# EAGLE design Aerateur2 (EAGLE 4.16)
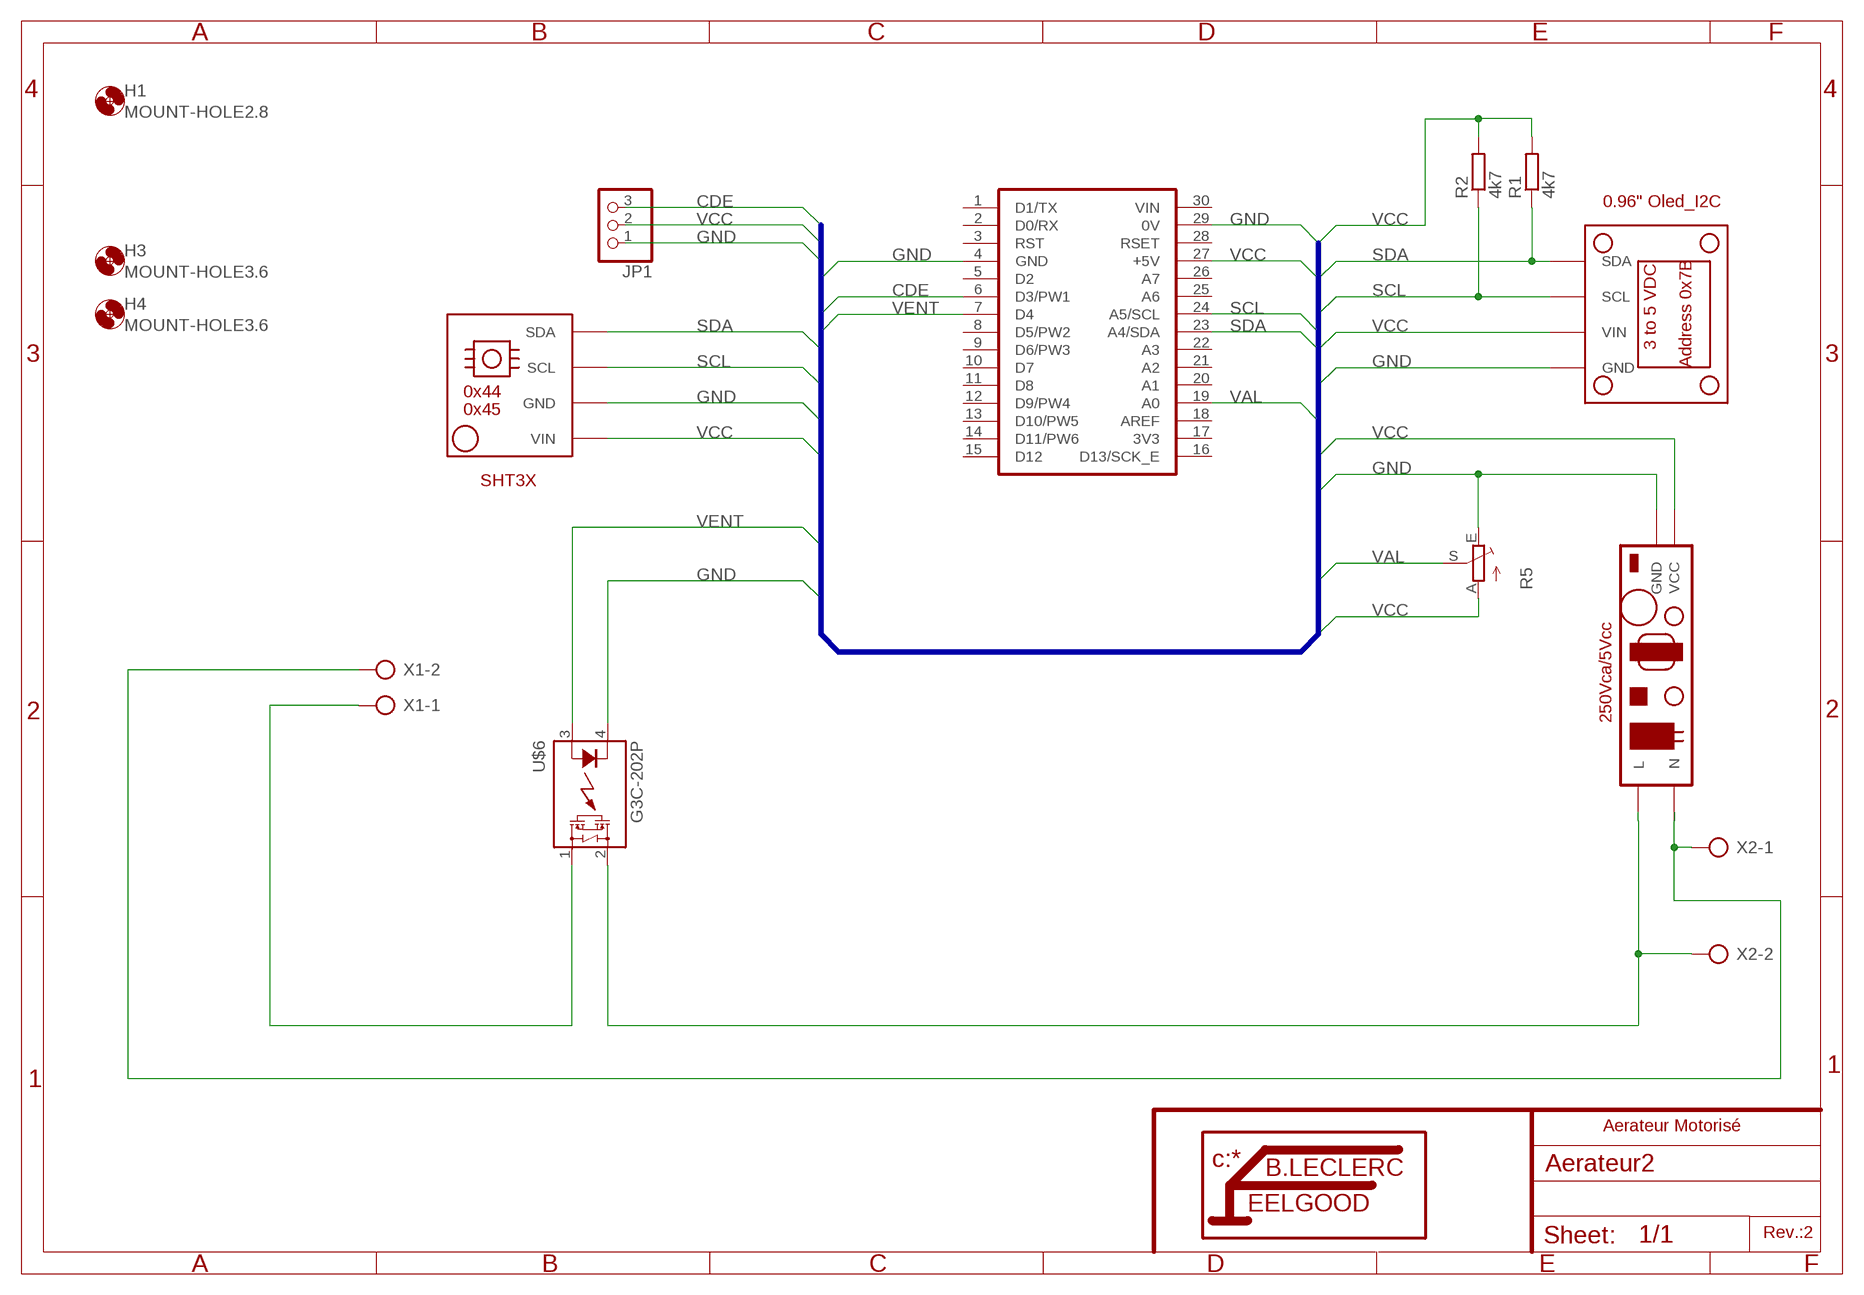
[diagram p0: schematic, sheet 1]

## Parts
H1  MOUNT-HOLE2.8  [2,8]
H3  MOUNT-HOLE3.6  [3,6]
H4  MOUNT-HOLE3.6  [3,6]
JP1  PINHD-1X3  [1X03]
R1  4k7  R-EU_M1206  [M1206]
R2  4k7  R-EU_M1206  [M1206]
R5  TRIM_EU-S63S  [S63S]
U1  NANO  [NANO]
U$2  SWPWR250-5ALIM  [SWPWR250-5ALIM]
U$3  OLED_I2C_DISPLAY  [OLED_I2C_DISPLAY]
U$4  SHT-3XD  [SHT-3XD]
U$6  G3C-202P  [G3C-202P]
X1  AK300/2  [AK300/2]
X2  AK300/2  [AK300/2]

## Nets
CDE: JP1.3 U1.6(D3/PW1)
GND: JP1.1 R5.E U1.4(GND) U1.29(0V) U$2.GND U$3.GND U$4.GND U$6.4(K)
N$1: U$6.1(DS1) X1.1
N$4: U$2.L U$6.2(DS2) X2.2
N$9: U$2.N X1.2 X2.1
SCL: R2.1 U1.24(A5/SCL) U$3.SCL U$4.SCL
SDA: R1.1 U1.23(A4/SDA) U$3.SDA U$4.SDA
VAL: R5.S U1.19(A0)
VCC: JP1.2 R1.2 R2.2 R5.A U1.27(+5V) U$2.VCC U$3.VIN U$4.VIN
VENT: U1.7(D4) U$6.3(A)
Unconnected: U1.1(D1/TX) U1.2(D0/RX) U1.3(RST) U1.5(D2) U1.8(D5/PW2) U1.9(D6/PW3) U1.10(D7) U1.11(D8) U1.12(D9/PW4) U1.13(D10/PW5) U1.14(D11/PW6) U1.15(D12) U1.16(D13/SCK_E) U1.18(AREF) U1.20(A1) U1.21(A2) U1.22(A3) U1.25(A6) U1.26(A7) U1.28(RSET)

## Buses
B$1

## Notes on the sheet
- Aerateur Motorisé
- Rev.:2

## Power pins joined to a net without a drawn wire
3V3: U1.17(3V3)
VIN: U1.30(VIN)

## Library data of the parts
H1 H3 H4 = holes:MOUNT-HOLE: MOUNTING HOLE with drill center marker
JP1 = pinhead:PINHD-1X3: PIN HEADER
R1 R2 = rcl:R-EU_: RESISTOR, European symbol
R5 = pot:TRIM_EU-: POTENTIOMETER
U1 = Arduino:NANO
U$2 = Arduino:SWPWR250-5ALIM
U$3 = Arduino:OLED_I2C_DISPLAY
U$4 = Arduino:SHT-3XD
U$6 = relay:G3C-202P
X1 X2 = con-ptr500:AK300/2: CONNECTOR

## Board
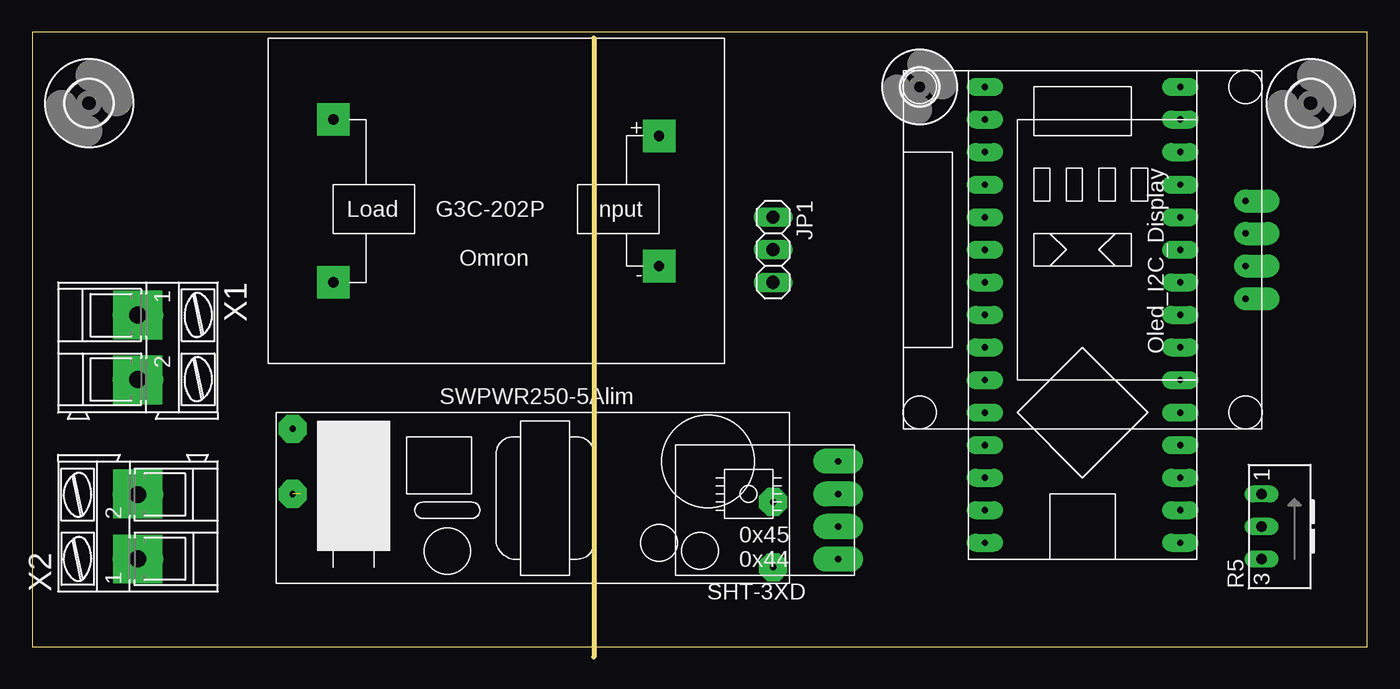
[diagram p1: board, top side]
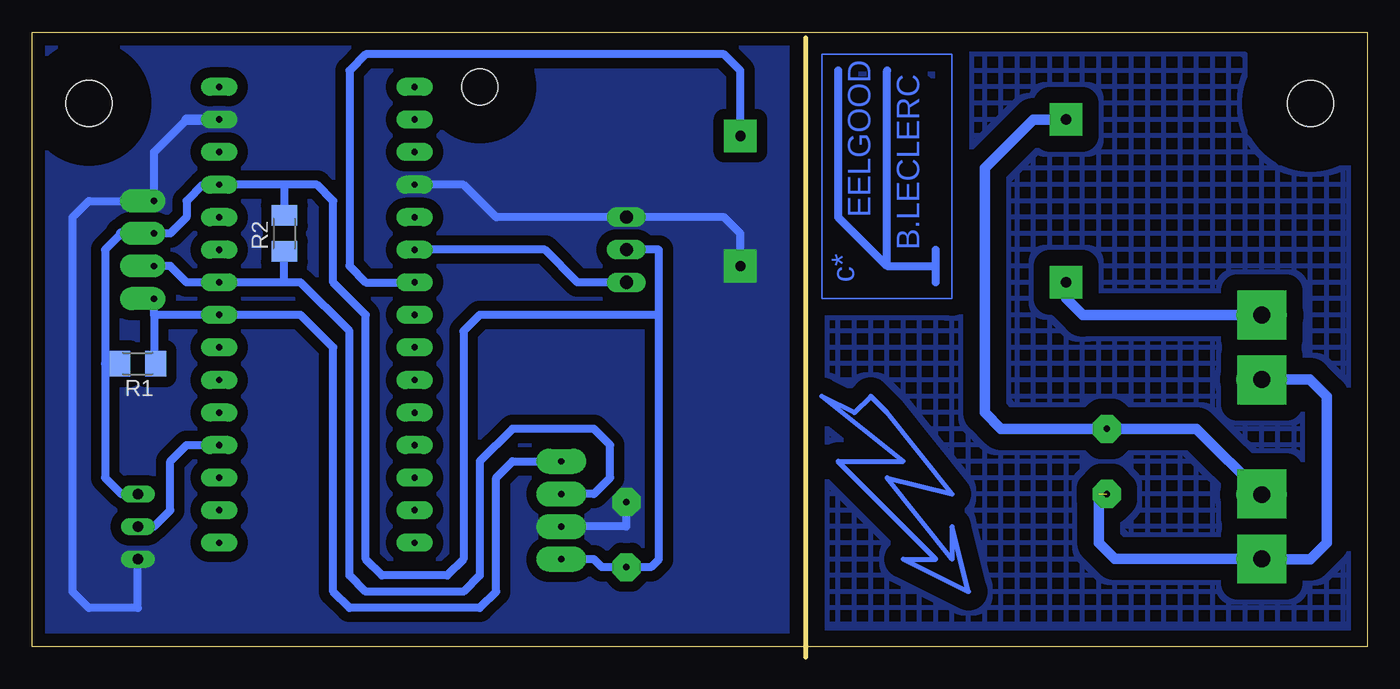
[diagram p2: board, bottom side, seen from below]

Size 104.12 x 48.73 mm. Coordinates in mm from the lower left corner, seen from the top.
Outline: 43.81,48.26 43.81,0
Outline: 0,0.8 104.12,0.8 104.12,48.73 0,48.73 0,0.8
Copper layers (1*16): Top 0.035mm / dielectric 1.5mm / Bottom 0.035mm
Design rules "default": minimum track width 10mil, minimum drill 24mil, track to track 8mil, track to pad 8mil, pad to pad 8mil, via to via 8mil, smd to smd 8mil, copper to edge 40mil, drill to drill 8mil, minimum pad ring 10mil, minimum via ring 8mil, stop-mask expansion 4mil, vias tented up to drill 0mil, thermal gap 10mil

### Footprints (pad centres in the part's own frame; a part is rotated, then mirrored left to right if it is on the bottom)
2,8 = hole 2.8: 0,0
3,6 = hole 3.6: 0,0
1X03 = drill 1.016 long: 1 -2.54,0; 2 0,0; 3 2.54,0
M1206 = smd 1.6 x 2: 1 -1.4,0; 2 1.4,0
S63S = drill 0.813 long: A 2.54,1.27; E -2.54,1.27; S 0,1.27
NANO = drill 0.5 pad 1.422 long: 1 -7.62,17.78; 2 -7.62,15.24; 3 -7.62,12.7; 4 -7.62,10.16; 5 -7.62,7.62; 6 -7.62,5.08; 7 -7.62,2.54; 8 -7.62,0; 9 -7.62,-2.54; 10 -7.62,-5.08; 11 -7.62,-7.62; 12 -7.62,-10.16; 13 -7.62,-12.7; 14 -7.62,-15.24; 15 -7.62,-17.78; 16 7.62,-17.78; 17 7.62,-15.24; 18 7.62,-12.7; 19 7.62,-10.16; 20 7.62,-7.62; 21 7.62,-5.08; 22 7.62,-2.54; 23 7.62,0; 24 7.62,2.54; 25 7.62,5.08; 26 7.62,7.62; 27 7.62,10.16; 28 7.62,12.7; 29 7.62,15.24; 30 7.62,17.78
SWPWR250-5ALIM = drill 0.5 pad 2.184 octagon: GND 19.05,-0.635; L -18.415,5.08; N -18.415,0; VCC 19.05,-5.715
OLED_I2C_DISPLAY = drill 0.5 pad 1.778 offset: GND 10.16,26.67; SCL 15.24,26.67; SDA 17.78,26.67; VIN 12.7,26.67
SHT-3XD = drill 0.5 pad 1.93 long: GND -2.54,1.27; SCL -2.54,-1.27; SDA -2.54,-3.81; VIN -2.54,3.81 | drill 0.5 pad 1.93 square: P$5 -2.54,3.81; P$6 -2.54,1.27
G3C-202P = drill 0.8 pad 2.54 square: 1 25.4,6.35; 2 25.4,-6.35; 3 0,-5.08; 4 0,5.08
AK300/2 = drill 1.321 long: 1 -2.515,0; 2 2.489,0

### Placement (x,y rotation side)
H1  69.21,44.45 0 top
H3  4.44,43.18 0 top
H4  99.69,43.18 0 top
JP1  57.78,31.75 270 top
R1  95.88,22.86 180 bottom
R2  84.45,33.02 90 bottom
R5  97.15,10.16 90 top
U1  81.91,26.67 0 top
U$2  38.73,12.7 0 top
U$3  67.94,45.72 270 top
U$4  60.32,11.43 180 top
U$5  [LITTFEEL]  29.84,30.48 90 bottom
U$6  48.89,35.56 180 top
X1  8.25,24.13 270 top
X2  8.25,10.16 90 top

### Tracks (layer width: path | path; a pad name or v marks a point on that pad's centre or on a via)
CDE
  Bottom 0.61: U1.6 64.13,31.75 61.59,29.21 JP1.3
GND  (via drill 0.5 pad 1.27)
  Bottom 0.61: U1.4 70.48,36.83 67.94,34.29 JP1.1 50.16,34.29 48.89,33.02 U$6.4 | 92.07,41.91 94.61,39.37 U$3.GND 99.69,35.56 100.96,34.29 100.96,5.08 99.69,3.81 95.88,3.81 R5.E | U$2.GND 58.41,12.06 57.78,11.43 57.78,10.16 U$4.GND
  Bottom 0.813: 92.07,41.91 U1.29
  other vias: 57.78,34.29 95.88,7.62 95.88,7.62
  pour Bottom (isolate 0.813, no thermals): 45.08,1.27 45.08,48.26 103.5,48.26 103.5,1.27
N$1
  Bottom 0.813: X1.1 22.2,26.64 23.49,27.94 U$6.1
N$3  (via drill 0.5 pad 3.81)
  other vias: 8.25,26.67
N$4
  Bottom 0.813: 19.68,17.78 13.33,17.78 8.25,12.7 X2.2 | 19.68,17.78 U$2.L | 19.68,17.78 28.57,17.78 29.84,19.05 29.84,38.1 26.03,41.91 U$6.2
N$8  (via drill 0.5 pad 3.81)
  other vias: 8.25,21.59
N$9  (1 unrouted)
  Bottom 0.813: 20.95,12.7 20.95,8.89 19.7,7.64 X2.1 8.25,7.62 4.44,7.62 3.17,8.89 3.17,20.32 4.49,21.64 X1.2 8.25,21.59
N$10  (via drill 0.5 pad 3.81)
  other vias: 8.25,12.7
N$11  (via drill 0.5 pad 3.81)
  other vias: 8.25,7.62
N$16
  pour Bottom (isolate 1.27, no thermals, hatched): 0.63,38.1 6.98,38.1 9.52,40.64 9.52,46.99 43.81,46.99 43.81,1.27 0.63,1.27
N$22  (via drill 0.5 pad 1.27)
  other vias: 57.78,31.75
N$23  (via drill 0.5 pad 1.27)
  other vias: 57.78,29.21
N$25  (via drill 0.5 pad 1.27)
  other vias: 95.88,10.16
N$37
  Bottom 0.406: 32.38,12.7 37.46,19.05 38.73,20.32 40,19.05 42.54,20.32 36.19,15.24 41.27,15.24 33.65,7.62 36.19,7.62 31.11,5.08 32.38,10.16 32.38,7.62 37.46,13.97 32.38,12.7
SCL
  Bottom 0.61: U$3.SCL 93.34,30.48 92.07,29.21 U1.24 84.45,29.21 | 84.45,29.21 83.18,29.21 79.37,25.4 79.37,6.35 78.1,5.08 70.48,5.08 69.21,6.35 69.21,15.24 66.67,17.78 60.32,17.78 59.05,16.51 59.05,13.97 60.32,12.7 U$4.SCL | 84.45,29.21 R2.1
SDA
  Bottom 0.61: 94.61,26.67 U1.23 83.18,26.67 80.64,24.13 80.64,5.08 79.37,3.81 69.21,3.81 67.94,5.08 67.94,13.97 66.67,15.24 U$4.SDA | R1.1 94.61,22.86 94.61,26.67 | 94.61,26.67 U$3.SDA
VAL
  Bottom 0.61: U1.19 92.07,16.51 93.34,15.24 93.34,11.43 94.61,10.16 R5.S
VCC  (via drill 0.5 pad 1.27)
  Bottom 0.61: U$3.VIN 93.34,33.02 92.07,34.29 92.07,35.56 90.8,36.83 U1.27 84.45,36.83 | R5.A 97.15,12.7 98.42,13.97 98.42,22.86 | 98.42,22.86 98.42,31.75 97.15,33.02 | 84.45,36.83 81.91,36.83 80.64,35.56 80.64,29.21 78.1,26.67 78.1,7.62 76.83,6.35 71.75,6.35 70.48,7.62 70.48,25.4 69.21,26.67 55.24,26.67 | 55.24,26.67 55.24,31.75 JP1.2 | 55.24,26.67 55.24,7.62 55.88,6.98 U$2.VCC 59.69,6.98 60.32,7.62 U$4.VIN | 84.45,36.83 R2.2 | 98.42,22.86 R1.2
  Bottom 0.813: U$3.VIN 97.15,33.02
  other vias: 95.88,12.7
VENT
  Bottom 0.61: U1.7 78.1,29.21 79.37,30.48 79.37,45.72 78.1,46.99 50.16,46.99 48.89,45.72 U$6.3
